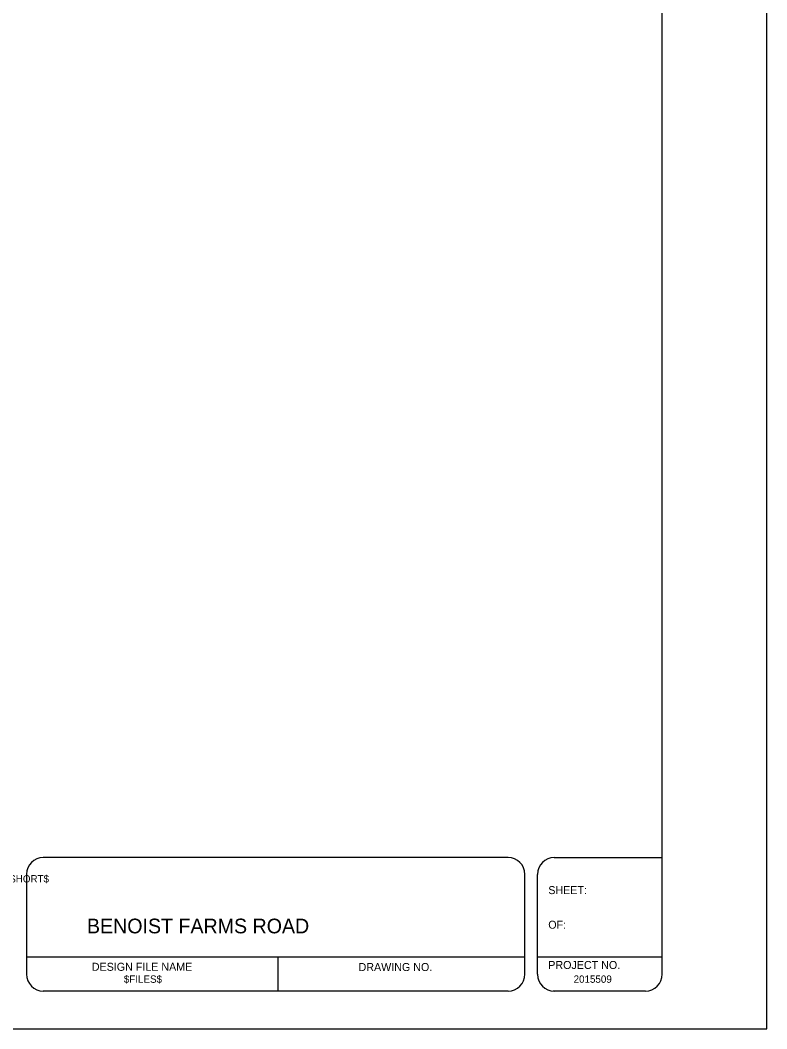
# Model space of a CAD drawing. Extents: x -0.7 to 16, y -0.9 to 9.7.
# Drawn here: x 12.02 to 15.95, y -0.9 to 4.4 of the extents above; entities that cross this region are included whole.
import ezdxf

# ---------------------------------------------------------------- set-up
doc = ezdxf.new("R2010")
doc.units = 0
for name, color, linetype in [('Default', 7, 'Continuous'), ('PlotBorder_dp', 7, 'Continuous'), ('TextMinor', 7, 'Continuous')]:
    doc.layers.add(name, color=color, linetype=linetype)

msp = doc.modelspace()

# ---------------------------------------------------------------- linework, layer by layer
at = {"layer": 'Default'}
for p, q in [((15.4, -0.6133), (15.4, 9.5065)), ((14.5898, 0), (12.146, 0)), ((14.8324, 0), (15.4, 0)), ((12.0578, -0.0882), (12.0578, -0.6131)), ((14.678, -0.6135), (14.678, -0.0884)), ((14.7442, -0.6135), (14.7442, -0.0884)), ((14.6769, -0.5241), (12.0568, -0.5241)), ((13.3801, -0.7005), (13.3801, -0.5241)), ((15.4, -0.5241), (14.7475, -0.5241)), ((14.5898, -0.7014), (12.146, -0.7014)), ((15.3118, -0.7015), (14.8271, -0.7015))]:
    msp.add_line(p, q, dxfattribs=at)
for centre, major_axis, start_param, end_param in [((12.146, -0.0882), (0, 0.0882), 0, 1.570796), ((14.5898, -0.0884), (0, 0.0882), 4.712389, 6.283185), ((14.8324, -0.0884), (0, -0.0882), 3.141593, 4.712389), ((12.146, -0.6131), (0, -0.0882), 4.712389, 6.283185), ((14.5898, -0.6131), (0, 0.0882), 3.141593, 4.712389), ((14.8324, -0.6135), (0, -0.0882), 4.712389, 6.283185), ((15.3118, -0.6133), (0, -0.0882), 0, 1.570796)]:
    msp.add_ellipse(centre, major_axis=major_axis, ratio=0.999927, start_param=start_param, end_param=end_param, dxfattribs=at)
at = {"layer": 'PlotBorder_dp'}
msp.add_lwpolyline([(-0.55, -0.9), (15.95, -0.9), (15.95, 9.7), (-0.55, 9.7)], close=True, dxfattribs=at)

# ---------------------------------------------------------------- texts
at = {"layer": 'Default'}
for s, height, p in [('SHEET:', 0.04207, (14.8009, -0.1922)), ('   BENOIST FARMS ROAD   ', 0.077091, (12.2895, -0.3982)), ('OF:', 0.04207, (14.8009, -0.374)), ('DESIGN FILE NAME', 0.042066, (12.4009, -0.5951)), ('DRAWING NO.', 0.042066, (13.8035, -0.5964)), ('PROJECT NO.', 0.042066, (14.8009, -0.5856)), ('$FILES$', 0.03855, (12.5694, -0.6581)), ('2015509', 0.03855, (14.9341, -0.6581))]:
    msp.add_text(s, height=height, dxfattribs=at).set_placement(p)
at = {"layer": 'TextMinor'}
msp.add_text('$SCALESHORT$', height=0.038546, dxfattribs=at).set_placement((11.7691, -0.1311))

doc.saveas('drawing.dxf')
